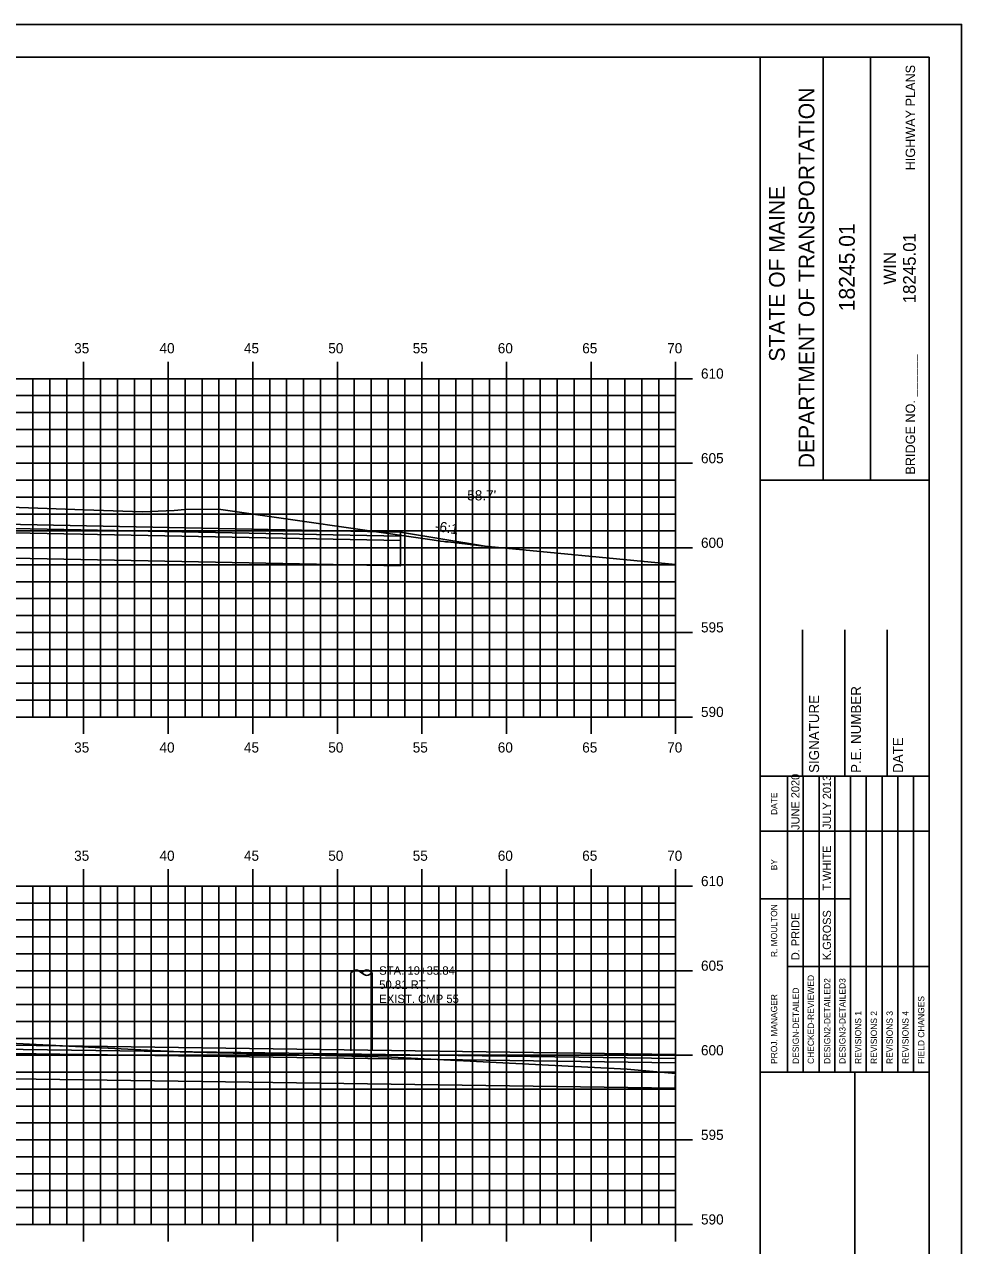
# Model space of a CAD drawing. Extents: x 1048141 to 1048311, y 780904 to 781014.
# Drawn here: x 1048255.2 to 1048310.6, y 780941.9 to 781014.1 of the extents above; entities that cross this region are included whole.
import ezdxf

# ---------------------------------------------------------------- set-up
doc = ezdxf.new("R2010")
doc.units = 0
for name, color, linetype in [('ANNOTATION', 7, 'Continuous'), ('BORDER', 7, 'Continuous'), ('D_Roadway_Centerline', 7, 'Continuous'), ('D_Roadway_Edge_Pavement', 7, 'Continuous'), ('D_Roadway_Pavement', 7, 'Continuous'), ('D_Roadway_SlopeLines', 7, 'Continuous'), ('D_Roadway_SubGrade', 7, 'Continuous'), ('D_Text_Monospaced', 7, 'Continuous'), ('Default', 7, 'Continuous'), ('H_V ANNOTATION', 7, 'Continuous'), ('MAJOR', 7, 'Continuous'), ('MINOR', 7, 'Continuous'), ('S_Roadway_Centerline', 7, 'Continuous'), ('S_Utilities_Pole_Joint', 7, 'Continuous'), ('S_Utilities_Pole_Power', 7, 'Continuous')]:
    doc.layers.add(name, color=color, linetype=linetype)

msp = doc.modelspace()

# ---------------------------------------------------------------- linework, layer by layer
at = {"layer": 'D_Roadway_Centerline'}
for points in [[(1048168.417, 780981.167), (1048206.016, 780984.768), (1048223.713, 780985.121), (1048277.445, 780984.047), (1048282.445, 780983.218)], [(1048169.913, 780954.819), (1048183.644, 780954.167), (1048223.713, 780954.151), (1048293.713, 780953.171)]]:
    msp.add_lwpolyline(points, dxfattribs=at)
at = {"layer": 'D_Roadway_Edge_Pavement'}
for points in [[(1048206.016, 780984.518), (1048206.016, 780984.768), (1048223.713, 780985.121), (1048277.445, 780984.047), (1048277.445, 780983.797), (1048223.713, 780984.871)], [(1048183.644, 780953.917), (1048183.644, 780954.167), (1048223.713, 780954.151), (1048293.713, 780953.171), (1048293.709, 780952.921), (1048223.713, 780953.901)]]:
    msp.add_lwpolyline(points, close=True, dxfattribs=at)
at = {"layer": 'D_Roadway_Pavement'}
for points in [[(1048206.016, 780984.268), (1048206.016, 780984.518), (1048223.713, 780984.871), (1048277.445, 780983.797), (1048277.445, 780983.547), (1048223.713, 780984.621)], [(1048183.644, 780953.667), (1048183.644, 780953.917), (1048223.713, 780953.901), (1048293.709, 780952.921), (1048293.706, 780952.671), (1048223.713, 780953.651)]]:
    msp.add_lwpolyline(points, close=True, dxfattribs=at)
at = {"layer": 'D_Roadway_SlopeLines'}
msp.add_lwpolyline([(1048277.445, 780984.047), (1048282.445, 780983.218)], dxfattribs=at)
at = {"layer": 'D_Roadway_SubGrade'}
for points in [[(1048206.016, 780982.768), (1048206.016, 780984.268), (1048223.713, 780984.621), (1048277.445, 780983.547), (1048277.445, 780982.047), (1048223.713, 780983.121)], [(1048183.644, 780952.167), (1048183.644, 780953.667), (1048223.713, 780953.651), (1048293.706, 780952.671), (1048293.685, 780951.171), (1048223.713, 780952.151)]]:
    msp.add_lwpolyline(points, close=True, dxfattribs=at)
at = {"layer": 'Default'}
for p, q in [((1048308.713, 781012.114), (1048148.713, 781012.114)), ((1048298.713, 780907.114), (1048298.713, 781012.117)), ((1048302.442, 780987.111), (1048302.442, 781012.111)), ((1048305.237, 780987.111), (1048305.237, 781012.111)), ((1048308.713, 780907.114), (1048308.713, 781012.114)), ((1048298.714, 780987.108), (1048308.713, 780987.108)), ((1048301.213, 780969.617), (1048301.213, 780978.265)), ((1048303.713, 780969.617), (1048303.713, 780978.265)), ((1048306.213, 780969.617), (1048306.213, 780978.265)), ((1048298.713, 780969.617), (1048308.713, 780969.617)), ((1048298.713, 780952.117), (1048308.713, 780952.117)), ((1048304.304, 780917.117), (1048304.304, 780952.117))]:
    msp.add_line(p, q, dxfattribs=at)
msp.add_lwpolyline([(1048140.62, 780904.055), (1048310.62, 780904.055), (1048310.62, 781014.055), (1048140.62, 781014.055)], close=True, dxfattribs=at)
for points in [[(1048300.328, 780966.367), (1048300.328, 780969.617)], [(1048301.261, 780952.12), (1048301.261, 780969.617)], [(1048302.192, 780969.617), (1048302.192, 780952.12)], [(1048303.124, 780952.12), (1048303.124, 780969.617)], [(1048304.056, 780952.12), (1048304.056, 780969.617)], [(1048304.987, 780952.12), (1048304.987, 780969.617)], [(1048305.919, 780952.12), (1048305.919, 780969.617)], [(1048306.851, 780952.12), (1048306.851, 780969.617)], [(1048307.782, 780952.12), (1048307.782, 780969.617)], [(1048300.329, 780952.12), (1048300.329, 780968.911)], [(1048298.713, 780966.367), (1048308.713, 780966.367)], [(1048298.713, 780962.367), (1048300.329, 780962.367)], [(1048300.328, 780962.367), (1048304.055, 780962.367)], [(1048300.328, 780958.367), (1048308.713, 780958.367)]]:
    msp.add_lwpolyline(points, dxfattribs=at)
at = {"layer": 'MAJOR'}
for p, q in [((1048258.713, 780994.116), (1048258.713, 780993.114)), ((1048263.713, 780994.116), (1048263.713, 780993.114)), ((1048268.713, 780994.116), (1048268.713, 780993.114)), ((1048273.713, 780994.116), (1048273.713, 780993.114)), ((1048278.713, 780994.116), (1048278.713, 780993.114)), ((1048283.713, 780994.116), (1048283.713, 780993.114)), ((1048288.713, 780994.116), (1048288.713, 780993.114)), ((1048293.713, 780994.116), (1048293.713, 780993.114)), ((1048153.713, 780993.114), (1048293.713, 780993.114)), ((1048153.713, 780993.114), (1048293.713, 780993.114)), ((1048258.713, 780973.114), (1048258.713, 780993.114)), ((1048263.713, 780973.114), (1048263.713, 780993.114)), ((1048268.713, 780973.114), (1048268.713, 780993.114)), ((1048273.713, 780973.114), (1048273.713, 780993.114)), ((1048278.713, 780973.114), (1048278.713, 780993.114)), ((1048283.713, 780973.114), (1048283.713, 780993.114)), ((1048288.713, 780973.114), (1048288.713, 780993.114)), ((1048294.715, 780993.114), (1048292.711, 780993.114)), ((1048293.713, 780973.114), (1048293.713, 780993.114)), ((1048293.713, 780973.114), (1048293.713, 780993.114)), ((1048153.713, 780988.114), (1048293.713, 780988.114)), ((1048294.715, 780988.114), (1048292.711, 780988.114)), ((1048153.713, 780983.114), (1048293.713, 780983.114)), ((1048294.715, 780983.114), (1048292.711, 780983.114)), ((1048153.713, 780978.114), (1048293.713, 780978.114)), ((1048294.715, 780978.114), (1048292.711, 780978.114)), ((1048153.713, 780973.114), (1048293.713, 780973.114)), ((1048153.713, 780973.114), (1048293.713, 780973.114)), ((1048258.713, 780972.112), (1048258.713, 780973.114)), ((1048263.713, 780972.112), (1048263.713, 780973.114)), ((1048268.713, 780972.112), (1048268.713, 780973.114)), ((1048273.713, 780972.112), (1048273.713, 780973.114)), ((1048278.713, 780972.112), (1048278.713, 780973.114)), ((1048283.713, 780972.112), (1048283.713, 780973.114)), ((1048288.713, 780972.112), (1048288.713, 780973.114)), ((1048294.715, 780973.114), (1048292.711, 780973.114)), ((1048293.713, 780972.112), (1048293.713, 780973.114)), ((1048258.713, 780964.116), (1048258.713, 780963.114)), ((1048263.713, 780964.116), (1048263.713, 780963.114)), ((1048268.713, 780964.116), (1048268.713, 780963.114)), ((1048273.713, 780964.116), (1048273.713, 780963.114)), ((1048278.713, 780964.116), (1048278.713, 780963.114)), ((1048283.713, 780964.116), (1048283.713, 780963.114)), ((1048288.713, 780964.116), (1048288.713, 780963.114)), ((1048293.713, 780964.116), (1048293.713, 780963.114)), ((1048153.713, 780963.114), (1048293.713, 780963.114)), ((1048153.713, 780963.114), (1048293.713, 780963.114)), ((1048258.713, 780943.114), (1048258.713, 780963.114)), ((1048263.713, 780943.114), (1048263.713, 780963.114)), ((1048268.713, 780943.114), (1048268.713, 780963.114)), ((1048273.713, 780943.114), (1048273.713, 780963.114)), ((1048278.713, 780943.114), (1048278.713, 780963.114)), ((1048283.713, 780943.114), (1048283.713, 780963.114)), ((1048288.713, 780943.114), (1048288.713, 780963.114)), ((1048294.715, 780963.114), (1048292.711, 780963.114)), ((1048293.713, 780943.114), (1048293.713, 780963.114)), ((1048293.713, 780943.114), (1048293.713, 780963.114)), ((1048153.713, 780958.114), (1048293.713, 780958.114)), ((1048294.715, 780958.114), (1048292.711, 780958.114)), ((1048153.713, 780953.114), (1048293.713, 780953.114)), ((1048294.715, 780953.114), (1048292.711, 780953.114)), ((1048153.713, 780948.114), (1048293.713, 780948.114)), ((1048294.715, 780948.114), (1048292.711, 780948.114)), ((1048153.713, 780943.114), (1048293.713, 780943.114)), ((1048153.713, 780943.114), (1048293.713, 780943.114)), ((1048258.713, 780942.112), (1048258.713, 780943.114)), ((1048263.713, 780942.112), (1048263.713, 780943.114)), ((1048268.713, 780942.112), (1048268.713, 780943.114)), ((1048273.713, 780942.112), (1048273.713, 780943.114)), ((1048278.713, 780942.112), (1048278.713, 780943.114)), ((1048283.713, 780942.112), (1048283.713, 780943.114)), ((1048288.713, 780942.112), (1048288.713, 780943.114)), ((1048294.715, 780943.114), (1048292.711, 780943.114)), ((1048293.713, 780942.112), (1048293.713, 780943.114))]:
    msp.add_line(p, q, dxfattribs=at)
at = {"layer": 'MINOR'}
for p, q in [((1048255.713, 780973.114), (1048255.713, 780993.114)), ((1048256.713, 780973.114), (1048256.713, 780993.114)), ((1048257.713, 780973.114), (1048257.713, 780993.114)), ((1048259.713, 780973.114), (1048259.713, 780993.114)), ((1048260.713, 780973.114), (1048260.713, 780993.114)), ((1048261.713, 780973.114), (1048261.713, 780993.114)), ((1048262.713, 780973.114), (1048262.713, 780993.114)), ((1048264.713, 780973.114), (1048264.713, 780993.114)), ((1048265.713, 780973.114), (1048265.713, 780993.114)), ((1048266.713, 780973.114), (1048266.713, 780993.114)), ((1048267.713, 780973.114), (1048267.713, 780993.114)), ((1048269.713, 780973.114), (1048269.713, 780993.114)), ((1048270.713, 780973.114), (1048270.713, 780993.114)), ((1048271.713, 780973.114), (1048271.713, 780993.114)), ((1048272.713, 780973.114), (1048272.713, 780993.114)), ((1048274.713, 780973.114), (1048274.713, 780993.114)), ((1048275.713, 780973.114), (1048275.713, 780993.114)), ((1048276.713, 780973.114), (1048276.713, 780993.114)), ((1048277.713, 780973.114), (1048277.713, 780993.114)), ((1048279.713, 780973.114), (1048279.713, 780993.114)), ((1048280.713, 780973.114), (1048280.713, 780993.114)), ((1048281.713, 780973.114), (1048281.713, 780993.114)), ((1048282.713, 780973.114), (1048282.713, 780993.114)), ((1048284.713, 780973.114), (1048284.713, 780993.114)), ((1048285.713, 780973.114), (1048285.713, 780993.114)), ((1048286.713, 780973.114), (1048286.713, 780993.114)), ((1048287.713, 780973.114), (1048287.713, 780993.114)), ((1048289.713, 780973.114), (1048289.713, 780993.114)), ((1048290.713, 780973.114), (1048290.713, 780993.114)), ((1048291.713, 780973.114), (1048291.713, 780993.114)), ((1048292.713, 780973.114), (1048292.713, 780993.114)), ((1048153.713, 780992.114), (1048293.713, 780992.114)), ((1048293.713, 780992.114), (1048292.711, 780992.114)), ((1048153.713, 780991.114), (1048293.713, 780991.114)), ((1048293.713, 780991.114), (1048292.711, 780991.114)), ((1048153.713, 780990.114), (1048293.713, 780990.114)), ((1048293.713, 780990.114), (1048292.711, 780990.114)), ((1048153.713, 780989.114), (1048293.713, 780989.114)), ((1048293.713, 780989.114), (1048292.711, 780989.114)), ((1048153.713, 780987.114), (1048293.713, 780987.114)), ((1048293.713, 780987.114), (1048292.711, 780987.114)), ((1048153.713, 780986.114), (1048293.713, 780986.114)), ((1048293.713, 780986.114), (1048292.711, 780986.114)), ((1048153.713, 780985.114), (1048293.713, 780985.114)), ((1048293.713, 780985.114), (1048292.711, 780985.114)), ((1048153.713, 780984.114), (1048293.713, 780984.114)), ((1048293.713, 780984.114), (1048292.711, 780984.114)), ((1048153.713, 780982.114), (1048293.713, 780982.114)), ((1048293.713, 780982.114), (1048292.711, 780982.114)), ((1048153.713, 780981.114), (1048293.713, 780981.114)), ((1048293.713, 780981.114), (1048292.711, 780981.114)), ((1048153.713, 780980.114), (1048293.713, 780980.114)), ((1048293.713, 780980.114), (1048292.711, 780980.114)), ((1048153.713, 780979.114), (1048293.713, 780979.114)), ((1048293.713, 780979.114), (1048292.711, 780979.114)), ((1048153.713, 780977.114), (1048293.713, 780977.114)), ((1048293.713, 780977.114), (1048292.711, 780977.114)), ((1048153.713, 780976.114), (1048293.713, 780976.114)), ((1048293.713, 780976.114), (1048292.711, 780976.114)), ((1048153.713, 780975.114), (1048293.713, 780975.114)), ((1048293.713, 780975.114), (1048292.711, 780975.114)), ((1048153.713, 780974.114), (1048293.713, 780974.114)), ((1048293.713, 780974.114), (1048292.711, 780974.114)), ((1048255.713, 780943.114), (1048255.713, 780963.114)), ((1048256.713, 780943.114), (1048256.713, 780963.114)), ((1048257.713, 780943.114), (1048257.713, 780963.114)), ((1048259.713, 780943.114), (1048259.713, 780963.114)), ((1048260.713, 780943.114), (1048260.713, 780963.114)), ((1048261.713, 780943.114), (1048261.713, 780963.114)), ((1048262.713, 780943.114), (1048262.713, 780963.114)), ((1048264.713, 780943.114), (1048264.713, 780963.114)), ((1048265.713, 780943.114), (1048265.713, 780963.114)), ((1048266.713, 780943.114), (1048266.713, 780963.114)), ((1048267.713, 780943.114), (1048267.713, 780963.114)), ((1048269.713, 780943.114), (1048269.713, 780963.114)), ((1048270.713, 780943.114), (1048270.713, 780963.114)), ((1048271.713, 780943.114), (1048271.713, 780963.114)), ((1048272.713, 780943.114), (1048272.713, 780963.114)), ((1048274.713, 780943.114), (1048274.713, 780963.114)), ((1048275.713, 780943.114), (1048275.713, 780963.114)), ((1048276.713, 780943.114), (1048276.713, 780963.114)), ((1048277.713, 780943.114), (1048277.713, 780963.114)), ((1048279.713, 780943.114), (1048279.713, 780963.114)), ((1048280.713, 780943.114), (1048280.713, 780963.114)), ((1048281.713, 780943.114), (1048281.713, 780963.114)), ((1048282.713, 780943.114), (1048282.713, 780963.114)), ((1048284.713, 780943.114), (1048284.713, 780963.114)), ((1048285.713, 780943.114), (1048285.713, 780963.114)), ((1048286.713, 780943.114), (1048286.713, 780963.114)), ((1048287.713, 780943.114), (1048287.713, 780963.114)), ((1048289.713, 780943.114), (1048289.713, 780963.114)), ((1048290.713, 780943.114), (1048290.713, 780963.114)), ((1048291.713, 780943.114), (1048291.713, 780963.114)), ((1048292.713, 780943.114), (1048292.713, 780963.114)), ((1048153.713, 780962.114), (1048293.713, 780962.114)), ((1048293.713, 780962.114), (1048292.711, 780962.114)), ((1048153.713, 780961.114), (1048293.713, 780961.114)), ((1048293.713, 780961.114), (1048292.711, 780961.114)), ((1048153.713, 780960.114), (1048293.713, 780960.114)), ((1048293.713, 780960.114), (1048292.711, 780960.114)), ((1048153.713, 780959.114), (1048293.713, 780959.114)), ((1048293.713, 780959.114), (1048292.711, 780959.114)), ((1048153.713, 780957.114), (1048293.713, 780957.114)), ((1048293.713, 780957.114), (1048292.711, 780957.114)), ((1048153.713, 780956.114), (1048293.713, 780956.114)), ((1048293.713, 780956.114), (1048292.711, 780956.114)), ((1048153.713, 780955.114), (1048293.713, 780955.114)), ((1048293.713, 780955.114), (1048292.711, 780955.114)), ((1048153.713, 780954.114), (1048293.713, 780954.114)), ((1048293.713, 780954.114), (1048292.711, 780954.114)), ((1048153.713, 780952.114), (1048293.713, 780952.114)), ((1048293.713, 780952.114), (1048292.711, 780952.114)), ((1048153.713, 780951.114), (1048293.713, 780951.114)), ((1048293.713, 780951.114), (1048292.711, 780951.114)), ((1048153.713, 780950.114), (1048293.713, 780950.114)), ((1048293.713, 780950.114), (1048292.711, 780950.114)), ((1048153.713, 780949.114), (1048293.713, 780949.114)), ((1048293.713, 780949.114), (1048292.711, 780949.114)), ((1048153.713, 780947.114), (1048293.713, 780947.114)), ((1048293.713, 780947.114), (1048292.711, 780947.114)), ((1048153.713, 780946.114), (1048293.713, 780946.114)), ((1048293.713, 780946.114), (1048292.711, 780946.114)), ((1048153.713, 780945.114), (1048293.713, 780945.114)), ((1048293.713, 780945.114), (1048292.711, 780945.114)), ((1048153.713, 780944.114), (1048293.713, 780944.114)), ((1048293.713, 780944.114), (1048292.711, 780944.114))]:
    msp.add_line(p, q, dxfattribs=at)
at = {"layer": 'S_Roadway_Centerline'}
for points in [[(1048196.003, 780985.718), (1048200.047, 780985.855), (1048204.657, 780986.031), (1048210.211, 780986.463), (1048217.23, 780986.949), (1048223.338, 780987.063), (1048230.229, 780987.172), (1048234.784, 780986.855), (1048242.494, 780986.262), (1048251.037, 780985.64), (1048258.754, 780985.363), (1048262.181, 780985.235), (1048264.072, 780985.322), (1048264.692, 780985.389), (1048266.688, 780985.402), (1048279.313, 780983.59), (1048279.814, 780983.509), (1048280.017, 780983.484), (1048280.104, 780983.476), (1048280.174, 780983.466), (1048280.269, 780983.46), (1048282.226, 780983.239), (1048293.713, 780982.125)], [(1048153.713, 780954.572), (1048159.825, 780954.58), (1048163.027, 780954.664), (1048167.266, 780954.693), (1048169.627, 780954.814), (1048180.042, 780954.995), (1048189.22, 780955.536), (1048196.477, 780955.609), (1048205.851, 780955.838), (1048213.438, 780955.489), (1048227.587, 780955.088), (1048240.634, 780954.526), (1048248.544, 780954.12), (1048264.413, 780953.312), (1048264.419, 780953.312), (1048264.422, 780953.313), (1048264.434, 780953.311), (1048276.919, 780952.999), (1048290.846, 780952.301), (1048293.713, 780952.036)]]:
    msp.add_lwpolyline(points, dxfattribs=at)
at = {"layer": 'S_Utilities_Pole_Joint'}
for p, q in [((1048274.518, 780958), (1048274.675, 780958.11)), ((1048274.987, 780958.11), (1048275.143, 780958)), ((1048275.3, 780958.11), (1048275.143, 780958)), ((1048275.143, 780958), (1048275.3, 780957.889)), ((1048275.768, 780958), (1048275.612, 780958.11)), ((1048275.612, 780957.889), (1048275.768, 780958))]:
    msp.add_line(p, q, dxfattribs=at)
for centre, start, end in [((1048274.831, 780957.889), 90, 125.26439), ((1048274.831, 780957.889), 54.73561, 90), ((1048275.456, 780957.889), 90, 125.26439), ((1048275.456, 780958.11), 234.73561, 270), ((1048275.456, 780957.889), 54.73561, 90), ((1048275.456, 780958.11), 270, 305.26439)]:
    msp.add_arc(centre, 0.271, start, end, dxfattribs=at)
at = {"layer": 'S_Utilities_Pole_Power'}
for p, q in [((1048274.518, 780953.38), (1048274.515, 780958)), ((1048275.768, 780953.38), (1048275.765, 780958))]:
    msp.add_line(p, q, dxfattribs=at)

# ---------------------------------------------------------------- texts
at = {"layer": 'ANNOTATION'}
for s, rotation, p in [("58.7'", 360, (1048281.394, 780985.918)), ('-6:1', 350.58872, (1048279.453, 780984.128))]:
    msp.add_text(s, height=0.6, rotation=rotation, dxfattribs=at).set_placement(p)
at = {"layer": 'BORDER'}
for s, p in [('DEPARTMENT OF TRANSPORTATION', (1048301.92, 780987.82)), ('STATE OF MAINE', (1048300.168, 780994.126))]:
    msp.add_text(s, height=0.93176, rotation=90, dxfattribs=at).set_placement(p)
at = {"layer": 'D_Text_Monospaced'}
for s, height, p in [('STA. 19+35.84', 0.49998, (1048276.185, 780957.878)), ('50.81 RT.', 0.5, (1048276.185, 780957.044)), ('EXIST. CMP 55', 0.49998, (1048276.185, 780956.204))]:
    msp.add_text(s, height=height, dxfattribs=at).set_placement(p)
at = {"layer": 'Default'}
for s, height, p in [('HIGHWAY PLANS', 0.55901, (1048307.871, 781005.43)), ('18245.01', 0.9318, (1048304.305, 780997.099)), ('18245.01', 0.7453, (1048307.909, 780997.564)), ('WIN', 0.7453, (1048306.75, 780998.672)), ('BRIDGE NO. ______', 0.55901, (1048307.871, 780987.445)), ('P.E. NUMBER', 0.59055, (1048304.674, 780969.809)), ('SIGNATURE', 0.5906, (1048302.194, 780969.809)), ('DATE', 0.5906, (1048307.154, 780969.809)), ('JUNE 2020', 0.4845, (1048301.036, 780966.442)), ('JULY 2013', 0.4845, (1048302.899, 780966.489)), ('DATE', 0.3714, (1048299.717, 780967.323)), ('T.WHITE', 0.4845, (1048302.899, 780962.852)), ('BY', 0.3714, (1048299.717, 780964.052)), ('R. MOULTON', 0.3727, (1048299.717, 780958.92)), ('D. PRIDE', 0.4845, (1048301.036, 780958.74)), ('K.GROSS', 0.4845, (1048302.899, 780958.74)), ('CHECKED-REVIEWED', 0.37275, (1048301.894, 780952.605)), ('DESIGN-DETAILED', 0.37275, (1048301, 780952.605)), ('DESIGN2-DETAILED2', 0.37275, (1048302.863, 780952.605)), ('DESIGN3-DETAILED3', 0.37275, (1048303.757, 780952.605)), ('PROJ. MANAGER', 0.37275, (1048299.717, 780952.605)), ('FIELD CHANGES', 0.37275, (1048308.416, 780952.605)), ('REVISIONS 1', 0.37275, (1048304.689, 780952.605)), ('REVISIONS 2', 0.37275, (1048305.621, 780952.605)), ('REVISIONS 3', 0.37275, (1048306.553, 780952.605)), ('REVISIONS 4', 0.37275, (1048307.484, 780952.605))]:
    msp.add_text(s, height=height, rotation=90, dxfattribs=at).set_placement(p)
at = {"layer": 'H_V ANNOTATION'}
for s, p in [('35', (1048258.154, 780994.614)), ('40', (1048263.199, 780994.614)), ('45', (1048268.191, 780994.614)), ('50', (1048273.178, 780994.614)), ('55', (1048278.17, 780994.614)), ('60', (1048283.199, 780994.614)), ('65', (1048288.191, 780994.614)), ('70', (1048293.215, 780994.614)), ('610', (1048295.213, 780993.114)), ('605', (1048295.213, 780988.114)), ('600', (1048295.213, 780983.114)), ('595', (1048295.213, 780978.114)), ('590', (1048295.213, 780973.114)), ('35', (1048258.154, 780971.014)), ('40', (1048263.199, 780971.014)), ('45', (1048268.191, 780971.014)), ('50', (1048273.178, 780971.014)), ('55', (1048278.17, 780971.014)), ('60', (1048283.199, 780971.014)), ('65', (1048288.191, 780971.014)), ('70', (1048293.215, 780971.014)), ('35', (1048258.154, 780964.614)), ('40', (1048263.199, 780964.614)), ('45', (1048268.191, 780964.614)), ('50', (1048273.178, 780964.614)), ('55', (1048278.17, 780964.614)), ('60', (1048283.199, 780964.614)), ('65', (1048288.191, 780964.614)), ('70', (1048293.215, 780964.614)), ('610', (1048295.213, 780963.114)), ('605', (1048295.213, 780958.114)), ('600', (1048295.213, 780953.114)), ('595', (1048295.213, 780948.114)), ('590', (1048295.213, 780943.114))]:
    msp.add_text(s, height=0.6, dxfattribs=at).set_placement(p)

doc.saveas('drawing.dxf')
